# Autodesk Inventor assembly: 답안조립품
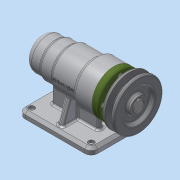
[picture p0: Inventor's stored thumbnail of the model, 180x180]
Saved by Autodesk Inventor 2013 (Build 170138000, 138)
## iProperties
Created: 2016-06
Part Number: 답안조립품
Document SubType Name: Assembly
Designer: dgall
Author: dgall
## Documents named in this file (12)
- C:\Users\dgall\Desktop\460607V1023\답안조립품.iam
- C:\Users\dgall\Desktop\460607V1023\본체.ipt
- C:\Users\dgall\Desktop\460607V1023\베어링 6004.ipt
- C:\Users\dgall\Desktop\460607V1023\축.ipt
- C:\Users\dgall\Desktop\460607V1023\커버.ipt
- C:\Users\dgall\Desktop\460607V1023\오일 실.ipt
- C:\Users\dgall\Desktop\460607V1023\키 5 x 5 x 16.ipt
- C:\Users\dgall\Desktop\460607V1023\V벨트풀리.ipt
- C:\Users\dgall\Desktop\460607V1023\멈춤나사 M3x8.ipt
- C:\Users\dgall\Desktop\460607V1023\어댑터슬리브.ipt
- C:\Users\dgall\Desktop\460607V1023\베어링 51202.ipt
- C:\Users\dgall\Desktop\460607V1023\볼트 M4 x 12.ipt
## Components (6 placed, 2 different names)
1. V벨트풀리:1 — 각도:3
2. ISO 4762 M4 x 12:1
3. ISO 4762 M4 x 12:2
4. ISO 4762 M4 x 12:3
5. ISO 4762 M4 x 12:4
6. ISO 4762 M4 x 12:5
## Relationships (1: Angle 1)
- 각도:3 [Angle]: V벨트풀리:1
